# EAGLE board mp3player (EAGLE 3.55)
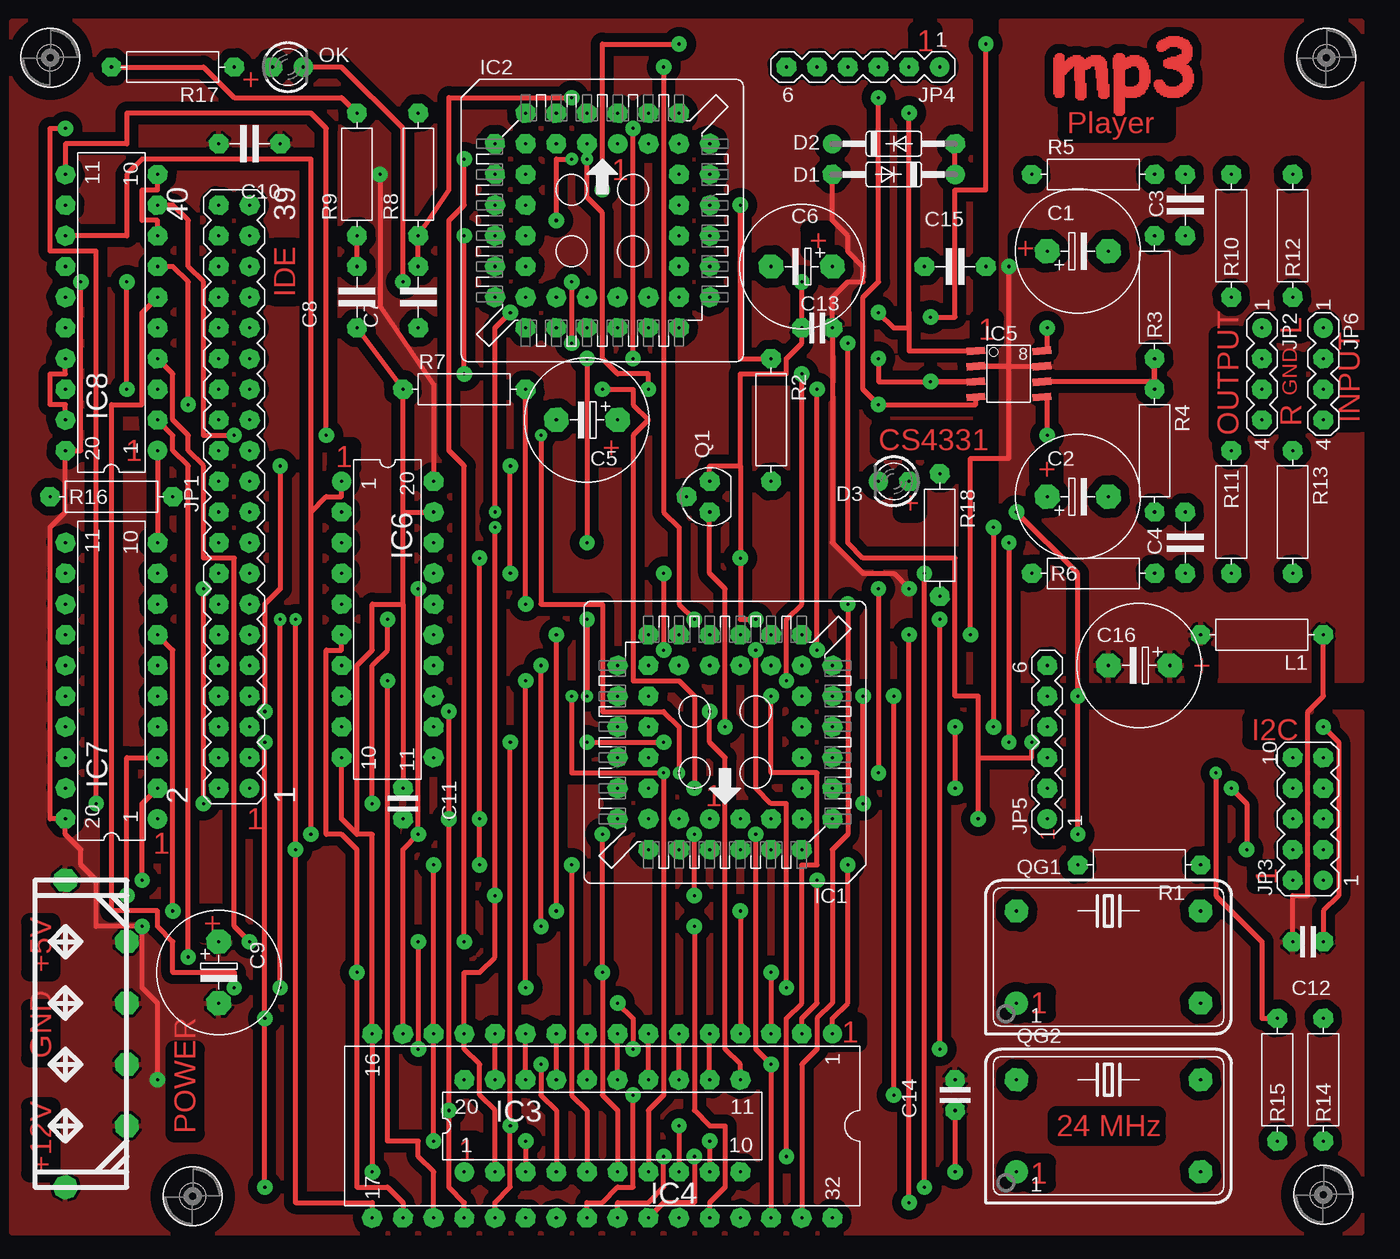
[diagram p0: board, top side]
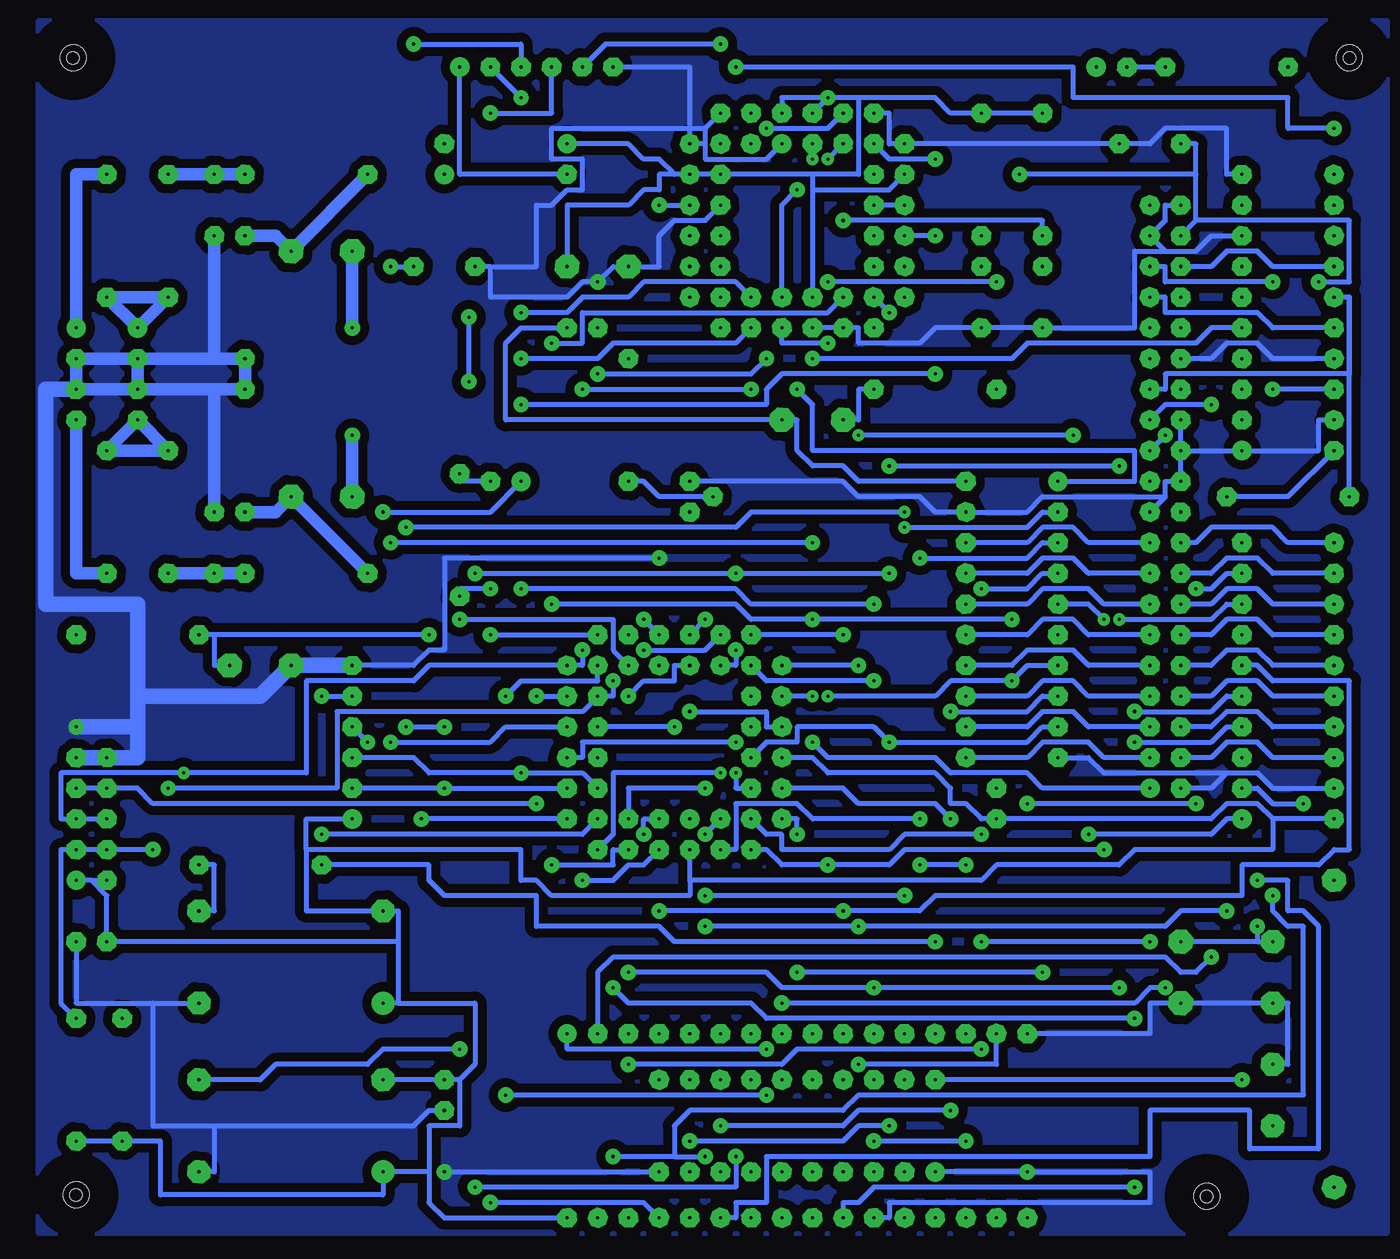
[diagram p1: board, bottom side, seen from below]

No outline drawn. Coordinates in mm, seen from the top.
Copper layers used: Top, Bottom

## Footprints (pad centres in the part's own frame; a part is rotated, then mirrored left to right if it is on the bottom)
-5 = drill 0.254 pad 2.007 octagon:  -2.54,0;  2.54,0
5 = drill 0.254 pad 1.6 octagon:  -2.54,0;  2.54,0
2,5 = drill 0.254 pad 1.6 octagon:  -1.27,0;  1.27,0
35-10 = drill 0.254 pad 1.6 round:  -5.08,0 | drill 0.254 pad 1.6 octagon:  5.08,0
D3 = drill 0.254 pad 1.6 octagon:  -1.27,0 | drill 0.254 pad 1.6 round:  1.27,0
CC44 = drill 0.254 pad 1.6 round:  0,0 | drill 0.254 pad 1.6 octagon:  -2.54,2.54;  -2.54,0;  -5.08,2.54;  -5.08,0;  -7.62,2.54;  -10.16,0;  -7.62,0;  -10.16,-2.54;  -7.62,-2.54;  -10.16,-5.08;  -7.62,-5.08;  -10.16,-7.62;  -7.62,-7.62;  -10.16,-10.16;  -7.62,-10.16;  -10.16,-12.7;  -7.62,-15.24;  -7.62,-12.7;  -5.08,-15.24;  -5.08,-12.7;  -2.54,-15.24;  -2.54,-12.7;  0,-15.24;  0,-12.7;  2.54,-15.24;  2.54,-12.7;  5.08,-15.24;  7.62,-12.7;  5.08,-12.7;  7.62,-10.16;  5.08,-10.16;  7.62,-7.62;  5.08,-7.62;  7.62,-5.08;  5.08,-5.08;  7.62,-2.54;  5.08,-2.54;  7.62,0;  5.08,2.54;  5.08,0;  2.54,2.54;  2.54,0;  0,2.54
L20 = drill 0.254 pad 1.6 round:  -11.43,-3.81 | drill 0.254 pad 1.6 octagon:  -8.89,-3.81;  -6.35,-3.81;  -3.81,-3.81;  -1.27,-3.81;  1.27,-3.81;  3.81,-3.81;  6.35,-3.81;  8.89,-3.81;  11.43,-3.81;  11.43,3.81;  8.89,3.81;  6.35,3.81;  3.81,3.81;  1.27,3.81;  -1.27,3.81;  -3.81,3.81;  -6.35,3.81;  -8.89,3.81;  -11.43,3.81
L32 = drill 0.254 pad 1.6 round:  0,0 | drill 0.254 pad 1.6 octagon:  2.54,0;  5.08,0;  7.62,0;  10.16,0;  12.7,0;  15.24,0;  17.78,0;  20.32,0;  22.86,0;  25.4,0;  27.94,0;  30.48,0;  33.02,0;  35.56,0;  38.1,0;  38.1,15.24;  35.56,15.24;  33.02,15.24;  30.48,15.24;  27.94,15.24;  25.4,15.24;  22.86,15.24;  20.32,15.24;  17.78,15.24;  15.24,15.24;  12.7,15.24;  10.16,15.24;  7.62,15.24;  5.08,15.24;  2.54,15.24;  0,15.24
-8 = smd 0.61 x 1.524 rotated 4.3:  -1.27,-2.743 | smd 0.61 x 1.524 rotated 4.9:  -1.27,2.743 | smd 0.61 x 1.524 rotated 4.4:  0,-2.743 | smd 0.61 x 1.524 rotated 4.5:  1.27,-2.743 | smd 0.61 x 1.524 rotated 4.8:  0,2.743 | smd 0.61 x 1.524 rotated 4.7:  1.27,2.743;  2.54,2.743 | smd 0.61 x 1.524 rotated 4.6:  2.54,-2.743
40 = drill 0.254 pad 1.6 round:  0,0 | drill 0.254 pad 1.6 octagon:  2.54,0;  5.08,0;  7.62,0;  10.16,0;  12.7,0;  0,2.54;  2.54,2.54;  5.08,2.54;  7.62,2.54;  10.16,2.54;  12.7,2.54;  15.24,0;  15.24,2.54;  17.78,0;  20.32,0;  22.86,0;  25.4,0;  27.94,0;  30.48,0;  17.78,2.54;  20.32,2.54;  22.86,2.54;  25.4,2.54;  27.94,2.54;  30.48,2.54;  33.02,0;  33.02,2.54;  35.56,0;  38.1,0;  40.64,0;  43.18,0;  45.72,0;  48.26,0;  35.56,2.54;  38.1,2.54;  40.64,2.54;  43.18,2.54;  45.72,2.54;  48.26,2.54
04-1 = drill 0.254 pad 1.6 round:  -3.81,0 | drill 0.254 pad 1.6 octagon:  -1.27,0;  1.27,0;  3.81,0
05-2 = drill 0.254 pad 1.6 round:  0,0 | drill 0.254 pad 1.6 octagon:  2.54,0;  5.08,0;  7.62,0;  10.16,0;  0,2.54;  2.54,2.54;  5.08,2.54;  7.62,2.54;  10.16,2.54
06-1 = drill 0.254 pad 1.6 round:  -6.35,0 | drill 0.254 pad 1.6 octagon:  -3.81,0;  -1.27,0;  1.27,0;  3.81,0;  6.35,0
10 = drill 0.254 pad 1.6 octagon:  -5.08,0;  5.08,0
IL-2 = hole 2.134: 0,0 | hole 1.016: 0,0
T54A = drill 0.254 pad 1.6 octagon:  -1.27,0;  0,1.905;  1.27,0
L14S = drill 0.254 pad 1.905 round:  -7.62,-3.81 | drill 0.254 pad 1.905 octagon:  7.62,-3.81;  7.62,3.81;  -7.62,3.81
CON = drill 0.254 pad 1.93 octagon:  2.54,0;  7.62,5.08;  7.62,10.16;  7.62,15.24;  7.62,20.32;  2.54,25.4

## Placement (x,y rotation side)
C1  10æ  [-5]  86.36,82.55 0 top
C2  10æ  [-5]  86.36,62.23 0 top
C3  680p  [5]  95.25,86.36 270 top
C4  680p  [5]  95.25,58.42 270 top
C5  10æ  [-5]  45.72,68.58 180 top
C6  10æ  [-5]  63.5,81.28 180 top
C7  10n  [5]  31.75,78.74 90 top
C8  2æ2  [5]  26.67,78.74 90 top
C9  10æ  [-5]  15.24,22.86 270 top
C10  100n  [5]  17.78,91.44 180 top
C11  100n  [2,5]  30.48,36.83 270 top
C12  100n  [2,5]  105.41,25.4 180 top
C13  100n  [2,5]  64.77,76.2 0 top
C14  100n  [2,5]  76.2,12.7 90 top
C15  100n  [5]  76.2,81.28 0 top
C16  10æ  [-5]  91.44,48.26 180 top
D1  1N4148  [35-10]  71.12,88.9 180 top
D2  1N4148  [35-10]  71.12,91.44 0 top
D3  LED 3 gn  [D3]  71.12,63.5 180 top
IC1  AT89S8252  [CC44]  55.88,35.56 180 top
IC2  MAS3507D  [CC44]  48.26,91.44 0 top
IC3  74hc573  [L20]  46.99,10.16 0 top
IC4  628128/512  [L32]  66.04,17.78 180 top
IC5  CS4331  [-8]  80.64,73.03 270 top
IC6  74ls245  [L20]  29.21,52.07 270 top
IC7  74ls245  [L20]  6.35,46.99 90 top
IC8  74ls244  [L20]  6.35,77.47 90 top
JP1  IDE_CON  [40]  17.78,38.1 90 top
JP2  OUT  [04-1]  101.6,72.39 270 top
JP3  I2C  [05-2]  106.68,30.48 90 top
JP4  DIGITAL  [06-1]  68.58,97.79 180 top
JP5  PROG  [06-1]  83.82,41.91 90 top
JP6  CD_IN  [04-1]  106.68,72.39 270 top
L1  100æH  [10]  101.6,50.8 180 top
LOCH1  [IL-2]  106.93,98.55 0 top
LOCH2  [IL-2]  1.27,98.55 0 top
LOCH3  [IL-2]  13.08,4.32 0 top
LOCH4  [IL-2]  106.68,4.45 0 top
OK  LED 3 gn  [D3]  20.95,97.79 0 top
Q1  BC548  [T54A]  55.88,62.23 90 top
QG1  14,318Mhz  [L14S]  88.9,24.13 0 top
QG2  24Mhz  [L14S]  88.9,10.16 0 top
R1  500  [10]  91.44,31.75 180 top
R2  10k  [10]  60.96,68.58 270 top
R3  56k  [10]  92.71,78.74 270 top
R4  56k  [10]  92.71,66.04 270 top
R5  2k2  [10]  87.63,88.9 0 top
R6  2k2  [10]  87.63,55.88 0 top
R7  18k  [10]  35.56,71.12 0 top
R8  10k  [10]  31.75,88.9 90 top
R9  1k  [10]  26.67,88.9 90 top
R10  10k  [10]  99.06,83.82 270 top
R11  10k  [10]  99.06,60.96 90 top
R12  10k  [10]  104.14,83.82 90 top
R13  10k  [10]  104.14,60.96 270 top
R14  10k  [10]  106.68,13.97 270 top
R15  10k  [10]  102.87,13.97 270 top
R16  10k  [10]  6.35,62.23 0 top
R17  1k  [10]  11.43,97.79 180 top
R18  1k  [10]  74.93,59.05 270 top
U$2  FLCON  [CON]  0,5.08 0 top

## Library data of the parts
C1-C16 L1 R1-R18 = DISCRETE
D1 D2 = DIODE
D3 OK = LED
IC1 IC2 IC4 JP1 U$2 = mp3
IC3 IC6-IC8 = 74XX
IC5 = SMD-IC
JP2-JP6 = CON-LSTB
LOCH1-LOCH4 = SPECIAL
Q1 = TRANS-SM
QG1 QG2 = QUARTZ

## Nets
3,3V: C6. D2. IC2. R8. R9. R17.
AD0: IC1. IC3. IC4. IC6.
AD1: IC1. IC3. IC4. IC6.
AD2: IC1. IC3. IC4. IC6.
AD3: IC1. IC3. IC4. IC6.
AD4: IC1. IC3. IC4. IC6.
AD5: IC1. IC3. IC4. IC6.
AD6: IC1. IC3. IC4. IC6.
AD7: IC1. IC3. IC4. IC6.
AD8: IC1. IC4. IC7.
AD9: IC1. IC4. IC7.
AD10: IC1. IC4. IC7.
AD11: IC1. IC4. IC7.
AD12: IC1. IC4. IC7.
AD13: IC1. IC4. IC7.
AD14: IC1. IC4. IC7.
AD15: IC1. IC4. IC7.
FILT+: C15. C16. IC5. L1.
GND: C3. C4. C6. C7. C8. C9. C10. C11. C12. C13. C14. C15. C16. IC1. IC2. IC3. IC4. IC5. IC6. IC7. IC8. JP1. JP2. JP3. JP4. JP5. JP6. Q1. QG1. QG2. R3. R4. R7. U$2.
IDE_ADR0: IC1. IC4. IC8.
IDE_ADR1: IC1. IC4. IC8.
IDE_ADR2: IC1. IC4. IC8.
IDE_ICHR: IC1. IC8.
IDE_IOR: IC1. IC6. IC7. IC8.
IDE_IOW: IC1. IC8.
IDE_RES: IC1. JP1.
INT: IC1. JP3.
MAS_DEM: IC2. R2.
MAS_SIC: IC1. IC2. JP5.
MAS_SID: IC1. IC2. JP5.
MEM_/RD: IC1. IC4.
MEM_/WR: IC1. IC4.
MEM_ALE: IC1. IC3.
N$1: IC2. IC5. JP4.
N$2: IC2. IC5. JP4.
N$3: IC2. IC5. JP4.
N$4: C1. IC5.
N$5: C2. IC5.
N$6: C1. R3. R5.
N$7: C2. R4. R6.
N$8: C3. R5. R10.
N$9: C4. R6. R11.
N$10: IC7. JP1.
N$11: JP2. R11. R13.
N$12: IC7. JP1.
N$13: IC7. JP1.
N$14: IC7. JP1.
N$15: IC7. JP1.
N$16: IC7. JP1.
N$17: IC2.
N$18: IC1. Q1.
N$19: IC1. QG2.
N$20: IC7. JP1.
N$21: Q1. R2.
N$22: QG1. R1.
N$23: IC2. R1.
N$24: IC7. JP1.
N$25: IC6. JP1.
N$26: IC6. JP1.
N$27: IC6. JP1.
N$28: IC6. JP1.
N$29: IC6. JP1.
N$30: IC6. JP1.
N$31: IC6. JP1.
N$32: IC6. JP1.
N$33: IC8. JP1.
N$34: IC8. JP1.
N$35: IC8. JP1.
N$36: IC8. JP1.
N$37: IC8. JP1.
N$38: IC8. JP1. R16.
N$39: C8. IC2. R9.
N$40: IC3. IC4.
N$41: D1. D2.
N$42: IC3. IC4.
N$43: C7. IC2. R8.
N$44: IC3. IC4.
N$45: IC3. IC4.
N$46: IC3. IC4.
N$47: IC3. IC4.
N$48: IC3. IC4.
N$49: IC3. IC4.
N$50: D3. R18.
N$51: JP2. R10. R12.
N$52: JP6. R12.
N$53: IC2. JP4.
N$54: JP6. R13.
N$55: IC2. OK.
N$56: OK. R17.
PRG_READ: D3. IC1. JP5.
RES: C5. IC1. JP5. R7.
SCL: IC1. IC2. JP3. R14.
SDA: IC1. IC2. JP3. R15.
VCC: C5. C9. C10. C11. C12. C13. C14. D1. IC1. IC3. IC4. IC6. IC7. IC8. JP1. JP3. JP4. JP5. L1. QG1. QG2. R14. R15. R16. R18. U$2.

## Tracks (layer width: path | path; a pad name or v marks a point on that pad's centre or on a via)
3,3V
  Top 0.406: R17. 13.97,97.79 16.51,95.25 25.4,95.25 R9.
  Bottom 0.406: R9. R8. 34.29,93.98 35.56,95.25 41.91,95.25 | 45.72,93.98 44.45,95.25 41.91,95.25 | 45.72,88.9 45.72,87.63 | 45.72,87.63 45.72,78.74 | 45.72,88.9 53.34,88.9 55.88,88.9 57.15,88.9 | 38.1,88.9 39.37,87.63 45.72,87.63 | 66.04,91.44 60.96,91.44 59.69,90.17 58.42,90.17 57.15,88.9 | 66.04,81.28 66.04,86.36 60.96,86.36 59.69,87.63 58.42,87.63 58.42,88.9 57.15,88.9 | 41.91,95.25 41.91,88.9 45.72,88.9
AD0  (via drill 0.25 pad 1.02, 0.25 pad 1.27)
  Top 0.406: 38.1,6.35 38.1,11.43 36.83,12.7 36.83,15.24 35.56,16.51 35.56,17.78 35.56,22.86 36.83,22.86 38.1,24.13 v38.1,29.21 v38.1,59.69 | v54.61,29.21 v54.61,34.29
  Bottom 0.406: 25.4,60.96 26.67,60.96 27.94,59.69 v38.1,59.69 | v54.61,34.29 53.34,35.56 | v38.1,29.21 v54.61,29.21
AD1  (via drill 0.25 pad 1.27)
  Top 0.406: v40.64,8.89 40.64,6.35 | v33.02,8.89 33.02,17.78 v33.02,31.75 | v36.83,57.15 v36.83,35.56 v36.83,31.75
  Bottom 0.406: v33.02,8.89 v40.64,8.89 | 25.4,58.42 26.67,58.42 27.94,57.15 v36.83,57.15 | v36.83,35.56 45.72,35.56 46.99,36.83 52.07,36.83 52.07,33.02 53.34,33.02 | v33.02,31.75 v36.83,31.75
AD2  (via drill 0.25 pad 1.27)
  Top 0.406: v41.91,15.24 41.91,12.7 43.18,11.43 43.18,6.35 | v31.75,54.61 v31.75,34.29 30.48,33.02 30.48,17.78
  Bottom 0.406: 30.48,17.78 30.48,15.24 v41.91,15.24 | 25.4,55.88 26.67,55.88 27.94,54.61 v31.75,54.61 | 50.8,35.56 49.53,34.29 48.26,34.29 48.26,33.02 39.37,33.02 38.1,34.29 v31.75,34.29
AD3  (via drill 0.25 pad 1.02, 0.25 pad 1.27)
  Top 0.406: 45.72,6.35 45.72,11.43 44.45,12.7 v44.45,31.75 | 27.94,2.54 27.94,3.81 21.59,3.81 v21.59,33.02 v21.59,52.07
  Bottom 0.406: 50.8,33.02 49.53,33.02 48.26,31.75 v44.45,31.75 39.37,31.75 38.1,33.02 v21.59,33.02 | v21.59,52.07 22.86,53.34 25.4,53.34
AD4  (via drill 0.25 pad 1.27)
  Top 0.406: 48.26,6.35 48.26,11.43 46.99,12.7 v46.99,22.86 v46.99,34.29 | 30.48,2.54 30.48,3.81 29.21,5.08 26.67,5.08 v26.67,22.86 26.67,33.02 25.4,34.29 24.13,34.29 24.13,49.53 25.4,49.53 25.4,50.8
  Bottom 0.406: v46.99,34.29 46.99,35.56 48.26,35.56 | v26.67,22.86 v46.99,22.86
AD5  (via drill 0.25 pad 1.02, 0.25 pad 1.27)
  Top 0.406: 50.8,6.35 50.8,11.43 52.07,12.7 v52.07,39.37 44.45,39.37 v44.45,45.72 | 33.02,2.54 33.02,6.35 31.75,7.62 31.75,8.89 29.21,8.89 v29.21,46.99
  Bottom 0.406: v52.07,39.37 52.07,38.1 50.8,38.1 | 25.4,48.26 27.94,48.26 v29.21,46.99 34.29,46.99 35.56,45.72 v44.45,45.72
AD6  (via drill 0.25 pad 1.27)
  Top 0.406: 35.56,2.54 35.56,3.81 34.29,5.08 v34.29,11.43 v34.29,35.56 v34.29,44.45 | v53.34,10.16 53.34,6.35
  Bottom 0.406: v34.29,35.56 35.56,36.83 41.91,36.83 43.18,38.1 48.26,38.1 | 25.4,45.72 26.67,45.72 27.94,44.45 v34.29,44.45 | v53.34,10.16 43.18,10.16 41.91,11.43 v34.29,11.43
AD7  (via drill 0.25 pad 1.27)
  Top 0.406: 38.1,2.54 38.1,3.81 39.37,5.08 v39.37,10.16 v39.37,41.91 | v55.88,8.89 55.88,6.35
  Bottom 0.406: 25.4,43.18 26.67,43.18 27.94,41.91 v39.37,41.91 40.64,43.18 46.99,43.18 46.99,41.91 49.53,41.91 50.8,40.64 | v55.88,8.89 43.18,8.89 41.91,10.16 v39.37,10.16
AD8  (via drill 0.25 pad 1.27)
  Top 0.406: 10.16,38.1 8.89,36.83 v8.89,30.48 | v54.61,52.07 53.34,53.34 53.34,59.69 52.07,60.96 v52.07,97.79 | v2.54,92.71 1.27,92.71 1.27,82.55 5.08,82.55 v5.08,36.83
  Bottom 0.406: v8.89,30.48 6.35,30.48 6.35,27.94 5.08,27.94 3.81,26.67 3.81,8.26 9.53,8.26 9.53,11.43 17.78,11.43 17.78,7.62 49.53,7.62 49.53,3.81 52.07,3.81 52.07,2.54 53.34,2.54 | v54.61,52.07 55.88,50.8 | v2.54,92.71 6.35,92.71 6.35,95.25 24.13,95.25 24.13,97.79 v52.07,97.79 | v5.08,36.83 7.62,36.83 8.89,38.1 10.16,38.1
AD9  (via drill 0.25 pad 1.27)
  Top 0.406: 50.8,2.54 52.07,3.81 54.61,3.81 v54.61,7.62 | v62.23,7.62 62.23,19.05 63.5,20.32 63.5,31.75 64.77,31.75 64.77,39.37 60.96,39.37 v60.96,45.72 | 10.16,40.64 7.62,40.64 v7.62,29.21
  Bottom 0.406: 57.15,7.62 v62.23,7.62 | 57.15,7.62 v54.61,7.62 | v60.96,45.72 59.69,46.99 57.15,46.99 57.15,48.26 55.88,48.26 | v7.62,29.21 7.62,27.94 6.35,26.67 5.08,26.67 5.08,12.7 41.91,12.7 43.18,11.43 55.88,11.43 57.15,10.16 57.15,7.62
AD10  (via drill 0.25 pad 1.27)
  Top 0.406: v19.05,5.08 v19.05,19.05 v19.05,41.91 | v59.69,49.53 59.69,38.1 60.96,36.83 62.23,36.83 v62.23,21.59
  Bottom 0.406: 10.16,43.18 11.43,43.18 12.7,41.91 v19.05,41.91 | v19.05,5.08 40.64,5.08 41.91,3.81 43.18,3.81 43.18,2.54 | 53.34,50.8 54.61,49.53 v59.69,49.53 | v62.23,21.59 60.96,20.32 50.8,20.32 49.53,19.05 v19.05,19.05
AD11  (via drill 0.25 pad 1.27)
  Top 0.406: 48.26,2.54 48.26,3.81 50.8,3.81 52.07,5.08 v52.07,7.62 | v73.66,5.08 v73.66,55.88 | v52.07,55.88 v52.07,49.53 | v19.05,44.45 19.05,53.34 20.32,54.61 v20.32,64.77 | v39.37,55.88 v39.37,64.77
  Bottom 0.406: v52.07,7.62 52.07,5.08 v73.66,5.08 | v73.66,55.88 v52.07,55.88 v39.37,55.88 | v52.07,49.53 52.07,48.26 53.34,48.26 | 10.16,45.72 11.43,45.72 12.7,44.45 v19.05,44.45 | v39.37,64.77 v20.32,64.77
AD12  (via drill 0.25 pad 1.27)
  Top 0.406: v58.42,27.94 58.42,17.78 | v43.18,27.94 v43.18,50.8
  Bottom 0.406: 10.16,48.26 8.89,48.26 7.62,46.99 1.27,46.99 1.27,33.02 2.54,33.02 3.81,31.75 10.16,31.75 10.16,29.21 35.56,29.21 36.83,27.94 v43.18,27.94 v58.42,27.94 | v43.18,50.8 50.8,50.8
AD13  (via drill 0.25 pad 1.27)
  Top 0.406: v41.91,26.67 v41.91,48.26 | v54.61,26.67 54.61,11.43 55.88,10.16 57.15,10.16 57.15,5.08 55.88,3.81 55.88,2.54 | 10.16,50.8 11.43,49.53 v11.43,27.94
  Bottom 0.406: v41.91,48.26 48.26,48.26 | v54.61,26.67 v41.91,26.67 16.51,26.67 15.24,27.94 v11.43,27.94
AD14  (via drill 0.25 pad 1.02, 0.25 pad 1.27)
  Top 0.406: v20.32,21.59 v20.32,52.07 | v60.96,22.86 60.96,17.78 | v40.64,21.59 v40.64,46.99
  Bottom 0.406: 10.16,53.34 11.43,53.34 12.7,52.07 v20.32,52.07 | v20.32,21.59 v40.64,21.59 48.26,21.59 49.53,22.86 v60.96,22.86 | 50.8,48.26 49.53,46.99 v40.64,46.99
AD15  (via drill 0.25 pad 1.02, 0.25 pad 1.27)
  Top 0.406: 63.5,2.54 63.5,15.24 64.77,16.51 64.77,19.05 66.04,20.32 66.04,33.02 67.31,34.29 v67.31,53.34 | v45.72,52.07 v45.72,45.72 | v13.97,36.83 v13.97,54.61 | v27.94,36.83 27.94,48.26 29.21,49.53 v29.21,52.07
  Bottom 0.406: v67.31,53.34 52.07,53.34 50.8,52.07 v45.72,52.07 v29.21,52.07 | v45.72,45.72 48.26,45.72 | 10.16,55.88 11.43,55.88 12.7,54.61 v13.97,54.61 | v13.97,36.83 v27.94,36.83
FILT+  (via drill 0.25 pad 1.27)
  Top 0.406: 80.64,73.03 v80.64,81.28 | 80.64,73.03 78.11,73.03 | 78.11,73.03 77.9,73.03 80.64,73.03 | 78.11,73.03 83.39,73.03 | 80.64,73.03 80.64,65.41 77.47,65.41 v77.47,50.8
  Bottom 0.406: 95.25,50.8 L1. | 95.25,50.8 95.25,48.26 93.98,48.26 | v77.47,50.8 95.25,50.8 | v80.64,81.28 C15.
  pour Top (isolate 0.75): 80.01,101.6 109.86,101.6 109.86,46.99 80.01,46.99
GND  (via drill 0.25 pad 1.27)
  Top 0.406: 76.2,11.43 v76.2,6.35 | v106.68,43.18 107.95,41.91 107.95,29.21 106.68,27.94 106.68,25.4 | 25.4,40.64 25.4,35.56 26.67,34.29 | 26.67,34.29 27.94,34.29 27.94,17.78 v27.94,6.35 | 10.16,83.82 10.16,85.09 8.89,85.09 8.89,87.63 10.16,87.63 10.16,88.9 | 10.16,66.04 10.16,58.42 | 2.54,73.66 2.54,72.39 1.27,72.39 1.27,69.85 2.54,69.85 2.54,68.58 | 30.48,60.96 30.48,71.12 26.67,76.2 | 30.48,53.34 30.48,60.96 | 30.48,53.34 30.48,38.1 | 30.48,60.96 33.02,60.96 | v59.69,52.07 58.42,52.07 v58.42,57.15 58.42,64.77 | 58.42,64.77 55.88,64.77 Q1. | 58.42,64.77 58.42,72.39 62.23,72.39 62.23,73.66 63.5,74.93 63.5,76.2 v63.5,80.01 | 26.67,34.29 26.67,48.26 27.94,49.53 27.94,53.34 30.48,53.34 | 83.39,71.75 92.71,71.75 R3. 92.71,71.12
  Bottom 0.406: 106.68,25.4 106.68,20.32 100.33,20.32 | 100.33,20.32 96.52,20.32 | v76.2,6.35 58.42,6.35 | 96.52,6.35 95.25,6.35 95.25,10.16 | 95.25,10.16 78.74,10.16 77.47,11.43 76.2,11.43 | 100.33,20.32 100.33,10.16 95.25,10.16 | 35.56,6.35 v27.94,6.35 17.78,6.35 17.78,3.81 39.37,3.81 39.37,2.54 40.64,2.54 | 2.54,38.1 7.62,38.1 8.89,39.37 11.43,39.37 | 11.43,39.37 12.7,38.1 15.24,38.1 | 25.4,40.64 22.86,40.64 21.59,39.37 11.43,39.37 | 7.62,15.24 6.35,15.24 6.35,20.32 7.62,20.32 C9. 17.78,20.32 17.78,17.78 27.94,17.78 | JP1. 16.51,86.36 16.51,85.09 17.78,83.82 16.51,82.55 | 16.51,82.55 13.97,82.55 12.7,83.82 10.16,83.82 | 40.64,93.98 39.37,93.98 39.37,91.44 38.1,91.44 20.32,91.44 17.78,91.44 16.51,92.71 11.43,92.71 11.43,88.9 10.16,88.9 | 16.51,62.23 17.78,60.96 | 16.51,62.23 16.51,63.5 15.24,63.5 15.24,66.04 | 2.54,68.58 3.81,68.58 3.81,66.04 10.16,66.04 15.24,66.04 | 15.24,66.04 15.24,68.58 | 15.24,73.66 12.7,73.66 11.43,74.93 8.89,74.93 7.62,73.66 2.54,73.66 | 48.26,91.44 49.53,90.17 54.61,90.17 54.61,91.44 | 54.61,91.44 55.88,91.44 55.88,97.79 JP4. | 54.61,92.71 54.61,91.44 | 54.61,92.71 53.34,93.98 | 53.34,86.36 54.61,85.09 57.15,85.09 58.42,83.82 58.42,81.28 C6. 62.23,81.28 v63.5,80.01 64.77,80.01 66.04,78.74 72.39,78.74 72.39,81.28 | 72.39,81.28 73.66,81.28 | 45.72,76.2 43.18,76.2 41.91,76.2 41.91,74.93 36.83,74.93 35.56,76.2 31.75,76.2 26.67,76.2 19.05,76.2 19.05,82.55 16.51,82.55 | Q1. 43.18,63.5 41.91,62.23 36.83,62.23 35.56,60.96 33.02,60.96 27.94,60.96 26.67,62.23 16.51,62.23 | v59.69,52.07 58.42,50.8 | 54.61,92.71 67.31,92.71 67.31,90.17 64.77,90.17 64.77,87.63 66.04,87.63 67.31,86.36 68.58,86.36 68.58,81.28 72.39,81.28
  Bottom 0.406: JP5. 78.74,48.26 77.47,49.53 76.2,49.53 76.2,57.15 v58.42,57.15
  Bottom 1.016: 101.6,73.66 106.68,73.66 106.68,71.12 101.6,71.12 | 101.6,71.12 101.6,73.66 | 101.6,71.12 95.25,71.12 | 95.25,73.66 R3. 92.71,71.12 95.25,71.12 | 101.6,73.66 95.25,73.66 | 95.25,73.66 C3. | 95.25,71.12 95.25,60.96
  Bottom 1.27: 106.68,40.64 JP3. 101.6,40.64 101.6,43.18 | JP5. C16. 91.44,45.72 101.6,45.72 | 101.6,45.72 101.6,43.18 | 101.6,43.18 v106.68,43.18 | 106.68,71.12 109.22,71.12 109.22,53.34 101.6,53.34 101.6,45.72
  pour Bottom (isolate 0.75): -1.91,101.6 109.86,101.6 109.86,1.27 -1.91,1.27
IDE_ADR0  (via drill 0.25 pad 1.27)
  Top 0.406: 10.16,68.58 11.43,67.31 11.43,66.04 12.7,64.77 v12.7,24.13 | v64.77,30.48 64.77,20.32 63.5,19.05 63.5,17.78
  Bottom 0.406: v12.7,24.13 13.97,22.86 15.24,22.86 16.51,24.13 62.23,24.13 63.5,22.86 63.5,17.78 | 58.42,33.02 59.69,31.75 60.96,31.75 62.23,30.48 v64.77,30.48
IDE_ADR1  (via drill 0.25 pad 1.27)
  Top 0.406: 60.96,2.54 v60.96,15.24 59.69,16.51 v59.69,34.29 | 10.16,73.66 11.43,72.39 11.43,68.58 12.7,67.31 12.7,66.04 13.97,64.77 13.97,57.15 16.51,57.15 16.51,26.67 v17.78,25.4 | v31.75,25.4 v31.75,16.51
  Bottom 0.406: v59.69,34.29 59.69,35.56 58.42,35.56 | v17.78,25.4 v31.75,25.4 | v31.75,16.51 46.99,16.51 48.26,15.24 v60.96,15.24
IDE_ADR2  (via drill 0.25 pad 1.27)
  Top 0.406: 66.04,17.78 66.04,19.05 67.31,20.32 v67.31,31.75 | 10.16,78.74 8.89,77.47 8.89,69.85 6.35,69.85 6.35,27.94 10.16,27.94 10.16,26.67 11.43,25.4 11.43,22.86 16.51,22.86 v16.51,21.59 | v48.26,20.32 49.53,19.05 v49.53,16.51
  Bottom 0.406: v67.31,31.75 62.23,31.75 62.23,33.02 60.96,33.02 | v16.51,21.59 17.78,21.59 19.05,20.32 v48.26,20.32 | v49.53,16.51 66.04,16.51 66.04,17.78
IDE_ICHR  (via drill 0.25 pad 1.27)
  Top 0.406: v45.72,73.66 v45.72,58.42 | v80.64,58.42 v80.64,41.91
  Bottom 0.406: 10.16,76.2 12.7,76.2 13.97,74.93 27.94,74.93 29.21,73.66 v45.72,73.66 | v45.72,58.42 v80.64,58.42 | v80.64,41.91 72.39,41.91 71.12,43.18 66.04,43.18
IDE_IOR  (via drill 0.25 pad 1.27)
  Top 0.406: v22.86,34.29 22.86,60.96 | 22.86,60.96 24.13,62.23 25.4,62.23 25.4,63.5 | v54.61,38.1 54.61,45.72 53.34,46.99 49.53,46.99 49.53,67.31 50.8,68.58 49.53,69.85 49.53,71.12 v46.99,71.12 | 2.54,83.82 7.62,83.82 7.62,88.9 8.89,90.17 22.86,90.17 22.86,60.96
  Bottom 0.406: 10.16,35.56 11.43,35.56 12.7,34.29 v22.86,34.29 | 60.96,35.56 60.96,38.1 v54.61,38.1 | v46.99,71.12 45.72,69.85 45.72,66.04 19.05,66.04 19.05,63.5 25.4,63.5
IDE_IOW  (via drill 0.25 pad 1.02, 0.25 pad 1.27)
  Top 0.406: v53.34,39.37 53.34,43.18 52.07,44.45 46.99,44.45 46.99,53.34 41.91,53.34 v41.91,67.31 | v24.13,67.31 24.13,92.71 22.86,93.98 7.62,93.98 7.62,91.44 2.54,91.44 2.54,88.9
  Bottom 0.406: 63.5,33.02 62.23,34.29 62.23,39.37 v53.34,39.37 | v24.13,67.31 v41.91,67.31
IDE_RES  (via drill 0.25 pad 1.27)
  Top 0.406: v45.72,41.91 v52.07,41.91
  Bottom 0.406: 17.78,38.1 26.67,38.1 27.94,39.37 34.29,39.37 35.56,40.64 44.45,40.64 v45.72,41.91 | v52.07,41.91 64.77,41.91 64.77,40.64 66.04,40.64
INT  (via drill 0.25 pad 1.27)
  Top 0.406: v68.58,36.83 v68.58,45.72
  Bottom 0.406: 106.68,38.1 104.14,38.1 101.6,38.1 100.33,36.83 v68.58,36.83 | v68.58,45.72 66.04,45.72
MAS_DEM  (via drill 0.25 pad 1.27)
  Top 0.406: 60.96,73.66 58.42,73.66 v58.42,86.36
  Bottom 0.406: v58.42,86.36 55.88,86.36
MAS_SIC  (via drill 0.25 pad 1.02, 0.25 pad 1.27)
  Top 0.406: v39.37,77.47 38.1,76.2 v38.1,60.96 | v79.38,59.69 v79.38,43.18 | v76.2,43.18 v76.2,38.1
  Bottom 0.406: v39.37,77.47 40.64,78.74 | v38.1,60.96 50.8,60.96 52.07,59.69 v79.38,59.69 | v79.38,43.18 v76.2,43.18 | 66.04,38.1 v76.2,38.1 83.82,38.1
MAS_SID  (via drill 0.25 pad 1.27)
  Top 0.406: v67.31,74.93 67.31,58.42 68.58,57.15 76.2,57.15 76.2,45.72 78.11,45.72 78.11,40.64 | v78.11,35.56 78.11,40.64 | v82.55,41.91 82.55,40.64 78.11,40.64
  Bottom 0.406: 43.18,78.74 44.45,77.47 64.77,77.47 64.77,74.93 v67.31,74.93 | 66.04,35.56 v78.11,35.56 | v82.55,41.91 83.82,43.18
MEM_/RD  (via drill 0.25 pad 1.27)
  Top 0.406: 45.72,2.54 45.72,3.81 46.99,3.81 48.26,5.08 49.53,5.08 v49.53,12.7 | v71.12,12.7 v71.12,45.72
  Bottom 0.406: v49.53,12.7 v71.12,12.7 | v71.12,45.72 69.85,46.99 63.5,46.99 63.5,48.26
MEM_/WR  (via drill 0.25 pad 1.27)
  Top 0.406: v72.39,3.81 v72.39,50.8
  Bottom 0.406: 58.42,2.54 59.69,3.81 v72.39,3.81 | v72.39,50.8 63.5,50.8
MEM_ALE  (via drill 0.25 pad 1.27)
  Top 0.406: 58.42,13.97 58.42,15.24 57.15,16.51 57.15,40.64 55.88,41.91 v55.88,44.45
  Bottom 0.406: v55.88,44.45 49.53,44.45 49.53,43.18 48.26,43.18
N$1  (via drill 0.25 pad 1.27)
  Top 0.406: v35.56,72.39 v35.56,83.82 | v69.85,95.25 69.85,80.01 68.58,78.74 68.58,71.12 v69.85,69.85 77.9,69.85 77.9,70.48
  Bottom 0.406: v35.56,83.82 38.1,83.82 | v35.56,72.39 48.26,72.39 49.53,71.12 49.53,69.85 v69.85,69.85 | v69.85,95.25 72.39,97.79
N$2  (via drill 0.25 pad 1.27)
  Top 0.406: v69.85,73.66 69.85,71.75 77.9,71.75 v74.17,71.75 | v78.74,99.69 78.74,87.63 76.2,87.63 76.2,77.09 v74.17,77.09
  Bottom 0.406: 50.8,76.2 52.07,74.93 62.23,74.93 63.5,73.66 v69.85,73.66 | v74.17,71.75 v74.17,77.09 | v78.74,99.69 69.85,99.69 69.85,97.79
N$3  (via drill 0.25 pad 1.27)
  Top 0.406: v69.85,77.47 71.12,76.2 72.39,76.2 72.39,77.47 | 72.39,77.47 v72.39,93.98 | 77.9,74.3 72.39,74.3 72.39,77.47
  Bottom 0.406: 50.8,78.74 52.07,80.01 59.69,80.01 60.96,78.74 64.77,78.74 66.04,77.47 v69.85,77.47 | v72.39,93.98 67.31,93.98 67.31,97.79
N$4  (via drill 0.25 pad 1.27)
  Top 0.406: 83.39,74.3 83.82,74.3 v83.82,76.2
  Bottom 1.016: v83.82,76.2 83.82,82.55
N$5  (via drill 0.25 pad 1.27)
  Top 0.406: IC5. 83.82,70.48 v83.82,67.31
  Bottom 1.016: 83.82,62.23 v83.82,67.31
N$6
  Bottom 1.016: 92.71,83.82 90.17,83.82 C1. 82.55,88.9
N$7
  Bottom 1.016: R4. 90.17,60.96 C2. 82.55,55.88
N$8
  Bottom 1.016: 99.06,88.9 95.25,88.9 R5.
N$9
  Bottom 1.016: 99.06,55.88 C4. R6.
N$10
  Bottom 0.406: 2.54,58.42 6.35,58.42 7.62,59.69 12.7,59.69 13.97,58.42 15.24,58.42
N$11
  Bottom 1.016: JP2. 104.14,66.04 R11. JP2.
N$12
  Bottom 0.406: 2.54,55.88 7.62,55.88 8.89,57.15 11.43,57.15 12.7,55.88 15.24,55.88
N$13
  Bottom 0.406: 2.54,53.34 7.62,53.34 8.89,54.61 11.43,54.61 12.7,53.34 15.24,53.34
N$14
  Bottom 0.406: 2.54,50.8 7.62,50.8 8.89,52.07 11.43,52.07 12.7,50.8 15.24,50.8
N$15
  Bottom 0.406: 2.54,48.26 7.62,48.26 8.89,49.53 11.43,49.53 12.7,48.26 15.24,48.26
N$16
  Bottom 0.406: 2.54,45.72 7.62,45.72 8.89,46.99 11.43,46.99 12.7,45.72 15.24,45.72
N$17
  Bottom 0.406: 38.1,86.36 40.64,86.36
N$18  (via drill 0.25 pad 1.27)
  Top 0.406: v57.15,43.18 57.15,54.61 55.88,55.88 55.88,60.96
  Bottom 0.406: v57.15,43.18 63.5,43.18
N$19  (via drill 0.25 pad 1.27)
  Top 0.406: v74.93,16.51 v74.93,52.07
  Bottom 0.406: 60.96,48.26 62.23,49.53 62.23,52.07 v74.93,52.07 | v74.93,16.51 81.28,16.51 82.55,15.24 90.17,15.24 91.44,13.97 96.52,13.97
N$20
  Bottom 0.406: 2.54,43.18 7.62,43.18 8.89,44.45 11.43,44.45 12.7,43.18 15.24,43.18
N$21
  Bottom 0.406: R2. 59.69,63.5 58.42,62.23 53.98,62.23
N$22
  Bottom 0.406: 96.52,31.75 95.25,31.75 95.25,27.94 96.52,27.94
N$23  (via drill 0.25 pad 1.27)
  Top 0.406: v35.56,90.17 35.56,86.36 34.29,85.09 34.29,66.04 35.56,64.77 v35.56,25.4
  Bottom 0.406: 40.64,91.44 39.37,90.17 v35.56,90.17 | v35.56,25.4 57.15,25.4 58.42,26.67 68.58,26.67 68.58,29.21 76.2,29.21 77.47,30.48 77.47,31.75 R1.
N$24
  Bottom 0.406: 2.54,40.64 7.62,40.64 8.89,41.91 11.43,41.91 12.7,40.64 15.24,40.64
N$25
  Bottom 0.406: 17.78,40.64 21.59,40.64 22.86,41.91 26.67,41.91 27.94,40.64 33.02,40.64
N$26
  Bottom 0.406: 17.78,43.18 22.86,43.18 24.13,44.45 26.67,44.45 27.94,43.18 33.02,43.18
N$27
  Bottom 0.406: 17.78,45.72 22.86,45.72 24.13,46.99 26.67,46.99 27.94,45.72 33.02,45.72
N$28
  Bottom 0.406: 17.78,48.26 22.86,48.26 24.13,49.53 27.94,49.53 29.21,48.26 33.02,48.26
N$29
  Bottom 0.406: 17.78,50.8 22.86,50.8 24.13,52.07 26.67,52.07 27.94,50.8 33.02,50.8
N$30
  Bottom 0.406: 17.78,53.34 21.59,53.34 22.86,54.61 26.67,54.61 27.94,53.34 33.02,53.34
N$31
  Bottom 0.406: 17.78,55.88 22.86,55.88 24.13,57.15 26.67,57.15 27.94,55.88 33.02,55.88
N$32
  Bottom 0.406: 17.78,58.42 22.86,58.42 24.13,59.69 26.67,59.69 27.94,58.42 33.02,58.42
N$33  (via drill 0.25 pad 1.27)
  Top 0.406: v7.62,71.12 v7.62,80.01
  Bottom 0.406: 2.54,71.12 v7.62,71.12 | v7.62,80.01 16.51,80.01 16.51,81.28 17.78,81.28
N$34
  Bottom 0.406: 2.54,76.2 7.62,76.2 8.89,77.47 16.51,77.47 16.51,78.74 17.78,78.74
N$35
  Bottom 0.406: 2.54,81.28 7.62,81.28 8.89,82.55 11.43,82.55 12.7,81.28 15.24,81.28
N$36  (via drill 0.25 pad 1.27)
  Top 0.406: v16.51,67.31 13.97,67.31 13.97,80.01 12.7,81.28 12.7,85.09 11.43,86.36 10.16,86.36
  Bottom 0.406: v16.51,67.31 17.78,66.04
N$37  (via drill 0.25 pad 1.27)
  Top 0.406: v12.7,69.85 12.7,80.01 11.43,81.28 10.16,81.28
  Bottom 0.406: 17.78,68.58 16.51,69.85 v12.7,69.85
N$38
  Bottom 0.406: 1.27,78.74 2.54,78.74 | 1.27,78.74 1.27,72.39 16.51,72.39 16.51,71.12 17.78,71.12 | 1.27,62.23 1.27,78.74
N$39  (via drill 0.25 pad 1.02, 0.25 pad 1.27)
  Top 0.406: C8. 26.67,83.82 | v44.45,90.17 43.18,90.17 v43.18,85.09
  Bottom 0.406: v44.45,90.17 43.18,91.44 | v43.18,85.09 26.67,85.09 26.67,83.82
N$40
  Top 0.406: 38.1,13.97 38.1,17.78
N$41
  Top 0.406: 76.2,88.9 D2.
N$42
  Top 0.406: 40.64,13.97 40.64,17.78
N$43  (via drill 0.25 pad 1.27)
  Top 0.406: C7. 31.75,83.82 34.29,87.63 34.29,95.25 v44.45,95.25
  Bottom 0.406: v44.45,95.25 48.26,95.25 IC2.
N$44
  Top 0.406: 43.18,13.97 43.18,17.78
N$45
  Top 0.406: 45.72,13.97 45.72,17.78
N$46
  Top 0.406: 48.26,13.97 48.26,17.78
N$47
  Top 0.406: 50.8,13.97 50.8,17.78
N$48
  Top 0.406: 53.34,13.97 53.34,17.78
N$49
  Top 0.406: 55.88,13.97 55.88,17.78
N$50
  Bottom 0.406: 72.39,63.5 74.93,63.5 74.93,64.14
N$51
  Bottom 1.016: R10. 104.14,78.74 101.6,76.2 R10.
N$52
  Bottom 1.016: 106.68,76.2 106.68,88.9 R12.
N$53  (via drill 0.25 pad 1.27)
  Top 0.406: v46.99,87.63 46.99,99.69 v53.34,99.69
  Bottom 0.406: 48.26,78.74 48.26,86.36 v46.99,87.63 | v53.34,99.69 62.87,99.69 64.77,97.79
N$54
  Bottom 1.016: JP6. 106.68,55.88 R13.
N$55  (via drill 0.25 pad 1.27)
  Top 0.406: v30.48,80.01 30.48,92.71 25.4,97.79 OK. | v44.45,80.01 v44.45,74.93
  Bottom 0.406: v30.48,80.01 v44.45,80.01 | v44.45,74.93 48.26,74.93 48.26,76.2
N$56
  Bottom 0.406: 16.51,97.79 19.68,97.79
PRG_READ  (via drill 0.25 pad 1.27)
  Top 0.406: v86.36,34.29 v86.36,45.72 86.36,55.88 v81.28,60.96
  Bottom 0.406: 63.5,35.56 64.77,34.29 v86.36,34.29 | v86.36,45.72 83.82,45.72 | D3. 72.39,60.96 v81.28,60.96
RES  (via drill 0.25 pad 1.27)
  Top 0.406: v40.64,53.34 R7. | v69.85,54.61 v69.85,39.37
  Bottom 0.406: R7. 41.91,71.12 41.91,68.58 C5. | 63.5,38.1 64.77,39.37 v69.85,39.37 77.47,39.37 78.74,40.64 83.82,40.64 | v40.64,53.34 50.8,53.34 52.07,54.61 v69.85,54.61
SCL  (via drill 0.25 pad 1.27)
  Top 0.406: v99.06,38.1 100.33,36.83 v100.33,33.02 | v49.53,73.66 v49.53,92.71 | v63.5,72.39 63.5,53.34 62.23,52.07 v62.23,46.99
  Bottom 0.406: v99.06,38.1 85.09,38.1 85.09,44.45 64.77,44.45 63.5,45.72 62.23,45.72 v62.23,46.99 | v100.33,33.02 104.14,33.02 106.68,33.02 107.95,33.02 107.95,20.32 106.68,19.05 | 43.18,93.98 44.45,92.71 v49.53,92.71 | v49.53,73.66 50.8,72.39 v63.5,72.39
SDA  (via drill 0.25 pad 1.02, 0.25 pad 1.27)
  Top 0.406: v45.72,90.17 45.72,87 46.99,85.72 46.99,73.66 48.26,72.39 50.8,72.39 v50.8,71.12 | v64.77,49.53 v64.77,71.12 | v97.79,39.37 97.79,29.21 101.6,25.4 101.6,19.05 102.87,19.05
  Bottom 0.406: 104.14,35.56 106.68,35.56 107.95,35.56 107.95,39.37 v97.79,39.37 87.63,39.37 87.63,46.99 78.74,46.99 77.47,48.26 66.04,48.26 64.77,48.26 v64.77,49.53 | v45.72,90.17 45.72,91.44 | v64.77,71.12 v50.8,71.12
VCC  (via drill 0.25 pad 1.27)
  Top 0.406: D1. 66.04,85.09 67.31,83.82 67.31,82.55 68.58,81.28 68.58,80.01 67.31,80.01 66.04,78.74 C13. 66.04,58.42 68.58,55.88 71.12,55.88 v72.39,54.61 | v28.57,88.9 28.57,77.98 33.02,71.5 IC6. | v10.16,13.97 10.16,20.32 8.89,21.59 v8.89,26.67 5.08,26.67 5.08,30.48 3.81,31.75 3.81,33.02 2.54,34.29 IC7. 1.27,35.56 1.27,59.69 2.54,60.96 IC8. 3.81,66.04 v3.81,80.01 | 106.68,50.8 106.68,45.72 105.41,44.45 105.41,29.21 104.14,29.21 C12.
  Bottom 0.406: D1. 74.93,88.9 74.93,97.79 | 13.97,85.09 15.24,83.82 | 13.97,88.9 13.97,91.44 C10. | 13.97,85.09 13.97,88.9 | IC6. 41.91,63.5 43.18,64.77 45.72,64.77 46.99,66.04 46.99,68.58 48.26,68.58 71.12,68.58 71.12,74.93 69.85,76.2 C13. | 13.97,88.9 v28.57,88.9 | 8.89,25.4 15.24,25.4 | 8.89,25.4 7.62,25.4 | IC7. 7.62,35.56 | 7.62,35.56 8.89,36.83 11.43,36.83 12.7,35.56 C11. 31.75,35.56 33.02,36.83 34.29,36.83 34.29,38.1 35.56,39.37 44.45,39.37 45.72,40.64 48.26,40.64 | v10.16,13.97 IC3. | v8.89,26.67 8.89,25.4 | 55.88,30.48 55.88,29.21 67.31,29.21 68.58,30.48 69.85,30.48 69.85,33.02 87.63,33.02 | 55.88,30.48 IC1. | 87.63,33.02 87.63,35.56 83.82,35.56 | 105.41,30.48 104.14,29.21 C12. 80.01,25.4 | 105.41,30.48 106.68,30.48 | 105.41,30.48 104.14,30.48 | IC4. 76.2,2.54 77.47,3.81 77.47,6.35 | 77.47,6.35 81.28,6.35 81.28,4.45 99.69,4.45 99.69,8.89 R15. R14. | QG2. C14. 74.93,13.97 | 80.01,20.32 81.28,20.32 | 80.01,25.4 80.01,27.94 QG1. 87.63,27.94 87.63,33.02 | 80.01,25.4 80.01,20.32 | 74.93,13.97 73.66,15.24 73.66,20.32 80.01,20.32 | 77.47,6.35 77.47,10.16 74.93,10.16 74.93,13.97 | 7.62,35.56 7.62,33.02 19.05,33.02 20.32,31.75 30.48,31.75 31.75,30.48 55.88,30.48 | 13.97,85.09 1.27,85.09 1.27,80.01 v3.81,80.01 | R16. 6.35,62.23 IC8. | v72.39,54.61 74.93,54.61 R18.
  pour Top (isolate 0.75): -1.91,101.6 77.47,101.6 77.47,44.45 109.86,44.45 109.86,1.27 -1.91,1.27
(copper drawn outside any net)
  shapes: Top area x233

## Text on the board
Top: 1 | + | Player | 1 | + | + | IDE | L | 1 | GND | R | INPUT | OUTPUT | CS4331 | 1 | 1 | + | + | + | + | I2C | 1 | 1 | 1 | 1 | 1 | + | +5V | 1 | 1 | GND | POWER | 24 MHz | 1 | +12V | 1
Measures: 100mm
